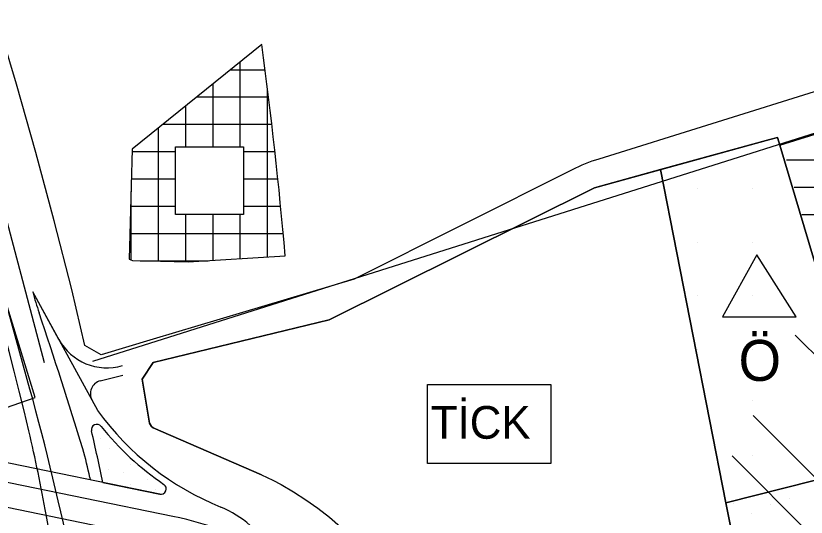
# Model space of a CAD drawing. Extents: x 409341 to 428634, y 4447481 to 4463281.
# Drawn here: x 420363.5 to 420653.1, y 4458345.7 to 4458529.4 of the extents above; entities that cross this region are included whole.
import ezdxf

# ---------------------------------------------------------------- set-up
doc = ezdxf.new("R2010")
doc.units = 0
for name, color, linetype in [('ADA', 7, 'Continuous'), ('ADAKENARI', 7, 'Continuous'), ('Default', 7, 'Continuous'), ('KALDIRIM', 7, 'Continuous'), ('Level 29', 7, 'Continuous'), ('LJ_SEMBOL', 7, 'Continuous'), ('OSB', 7, 'Continuous'), ('PL_AYA_PARK_DINLENME', 7, 'Continuous'), ('PL_EĞİTİM', 7, 'Continuous'), ('PL_KON_ONE_250', 7, 'Continuous'), ('PL_TİCK', 7, 'Continuous'), ('RAYLI_TOPLU_TAŞIMA_HATTI', 7, 'Continuous'), ('SN_BELEDIYE', 7, 'Continuous'), ('SN_TR_SIVILASMA', 7, 'Continuous'), ('TR_AKARYAKIT_SERVİS', 7, 'Continuous'), ('TR_EĞİTİM', 7, 'Continuous'), ('TR_ORTAGELISME', 7, 'Continuous'), ('TR_PARKALANI', 7, 'Continuous'), ('TR_TALIISMERK', 7, 'Continuous'), ('TR_TİCK', 7, 'Continuous')]:
    doc.layers.add(name, color=color, linetype=linetype)

# ---------------------------------------------------------------- blocks, each defined once
blk = doc.blocks.new('POINT_DISPLAY')
at = {"layer": 'Default'}
blk.add_line((0, 0), (0, 0), dxfattribs=at)

msp = doc.modelspace()

# ---------------------------------------------------------------- linework, layer by layer
at = {"layer": 'ADA'}
for p, q in [((420643.44, 4458481.99), (420732.53, 4458509.85)), ((420632.89, 4458304.12), (420599.65, 4458473.08))]:
    msp.add_line(p, q, dxfattribs=at)
for points in [[(420643.44, 4458481.99), (420659.49, 4458427.94), (420675.59, 4458370.42), (420677.32, 4458364.26), (420677.56, 4458363.39)], [(420623.66, 4458351.01), (420677.24, 4458364.55)]]:
    msp.add_lwpolyline(points, dxfattribs=at)
at = {"layer": 'ADAKENARI'}
for p, q in [((420847.49, 4458561.51), (420577.09, 4458476.96)), ((420363.78, 4458504.36), (420356.29, 4458529.2)), ((420370.89, 4458479.41), (420363.78, 4458504.36)), ((420575.45, 4458466.45), (420639.77, 4458484.06)), ((420575.45, 4458466.45), (420639.77, 4458484.06)), ((420639.77, 4458484.06), (420642.58, 4458484.9)), ((420642.58, 4458484.9), (420643.44, 4458481.99)), ((420377.62, 4458454.35), (420370.89, 4458479.41)), ((420567.31, 4458473.01), (420487.46, 4458432.9)), ((420383.98, 4458429.2), (420377.62, 4458454.35)), ((420487.46, 4458432.9), (420413.82, 4458410.91)), ((420388.84, 4458408.66), (420383.98, 4458429.2)), ((420394.78, 4458405.23), (420388.84, 4458408.66)), ((420413.82, 4458410.91), (420394.78, 4458405.23)), ((420413.22, 4458378.93), (420412.48, 4458380.21)), ((420416.22, 4458354.12), (420305.83, 4458376.8)), ((420416.22, 4458354.12), (420305.83, 4458376.8)), ((420413.84, 4458378.43), (420413.22, 4458378.93)), ((420453.57, 4458361.2), (420413.84, 4458378.43))]:
    msp.add_line(p, q, dxfattribs=at)
msp.add_lwpolyline([(420453.57, 4458361.2), (420457.65, 4458359.25), (420460.66, 4458357.68), (420465.3, 4458355), (420469.81, 4458352.11), (420474.18, 4458349.01), (420478.39, 4458345.7), (420482.45, 4458342.2), (420486.33, 4458338.51), (420490.35, 4458333.66), (420496.8, 4458325.83), (420501.73, 4458320.76), (420507.72, 4458316.16), (420514.7, 4458311.48), (420516.88, 4458310.01), (420522, 4458308.44), (420551.88, 4458303.07)], dxfattribs=at)
for centre, radius, start, end in [((420596.48, 4458414.92), 65, 107.3623, 116.6696), ((420393.2, 4458377.74), 2, 38.6563, 192.9963), ((420393.2, 4458377.74), 2, 38.6563, 192.9963), ((419493.85, 4458170.17), 921, 11.79266, 12.99632), ((419493.85, 4458170.17), 921, 11.79266, 12.99632), ((420476.76, 4458444.58), 105, 218.6563, 235.8038), ((420476.76, 4458444.58), 105, 218.6563, 235.8038), ((420416.62, 4458356.08), 2, 258.3886, 55.8038), ((420416.62, 4458356.08), 2, 258.3886, 55.8038)]:
    msp.add_arc(centre, radius, start, end, dxfattribs=at)
at = {"layer": 'KALDIRIM'}
for p, q in [((420379.27, 4458410.87), (420369.76, 4458428.28)), ((420393.5, 4458384.8), (420369.76, 4458428.28)), ((420379.27, 4458410.87), (420369.76, 4458428.28)), ((420393.5, 4458384.8), (420369.76, 4458428.28)), ((420421.02, 4458345.99), (420060.88, 4458419.99)), ((420421.02, 4458345.99), (420060.88, 4458419.99)), ((420423.3, 4458336.33), (420043.3, 4458414.41)), ((420423.3, 4458336.33), (420043.3, 4458414.41)), ((420394.42, 4458395.73), (420402.69, 4458397.74)), ((420393.5, 4458384.8), (420391.46, 4458388.54)), ((420390.62, 4458360.24), (420390.79, 4458359.35)), ((420390.62, 4458360.24), (420390.79, 4458359.35))]:
    msp.add_line(p, q, dxfattribs=at)
for centre, radius, start, end in [((420466.74, 4458452.67), 100, 194.1286, 198.7088), ((420466.74, 4458452.67), 100, 194.1286, 198.7088), ((418798.88, 4457887.84), 1660.9, 16.90173, 18.70883), ((418798.88, 4457887.84), 1660.9, 16.90173, 18.70883), ((420396.82, 4458420.45), 20, 208.633, 286.6245), ((420396.82, 4458420.45), 20, 208.633, 286.6245), ((420395.85, 4458390.94), 5, 106.6245, 208.633), ((420395.85, 4458390.94), 5, 106.6245, 208.633), ((420476.76, 4458444.58), 102.5, 215.6789, 248.1673), ((420476.76, 4458444.58), 102.5, 215.6789, 248.1673), ((420292.36, 4458341.64), 100, 10.7174, 16.9017), ((420292.36, 4458341.64), 100, 10.7174, 16.9017), ((420424.43, 4458315.18), 37.08, 28.2412, 67.4666), ((420424.43, 4458315.18), 37.08, 28.2412, 67.4666), ((420395.06, 4458219.63), 129, 40.973, 78.3886), ((420395.06, 4458219.63), 129, 40.973, 78.3886)]:
    msp.add_arc(centre, radius, start, end, dxfattribs=at)
at = {"layer": 'Level 29'}
for p, q in [((420478.28, 4458418.07), (420575.45, 4458466.45)), ((420413.8, 4458402.43), (420478.28, 4458418.07)), ((420409.77, 4458396.32), (420413.8, 4458402.43)), ((420412.48, 4458380.21), (420409.77, 4458396.32))]:
    msp.add_line(p, q, dxfattribs=at)
at = {"layer": 'LJ_SEMBOL'}
for p, q in [((420634.93, 4458441.88), (420622.38, 4458419.07)), ((420649.4, 4458419.07), (420634.93, 4458441.88)), ((420622.38, 4458419.07), (420649.4, 4458419.07))]:
    msp.add_line(p, q, dxfattribs=at)
at = {"layer": 'OSB'}
for points in [[(420374, 4458402.25), (420333.73, 4458554.43), (420007.65, 4459406.75), (419828, 4459907.45), (419873.71, 4459964.63), (419861.99, 4460046.05), (419800.79, 4460096.52), (419788.07, 4460171.32), (419687.29, 4460251.24), (419645.19, 4460319.68), (419562.32, 4460570.29)], [(421303.14, 4458521.03), (421213.37, 4458544.99), (420881.63, 4458557.8), (420391.63, 4458402.74)]]:
    msp.add_lwpolyline(points, dxfattribs=at)
at = {"layer": 'PL_AYA_PARK_DINLENME'}
for points in [[(420651.06, 4458305.46), (420782.27, 4458335.25), (420761.16, 4458405.89), (420743.03, 4458396.67), (420723.36, 4458386.67), (420703.69, 4458376.67), (420677.56, 4458363.39), (420677.32, 4458364.26), (420677.24, 4458364.55), (420623.66, 4458351.01), (420632.89, 4458304.12)], [(420395.41, 4458358.4), (420416.22, 4458354.12)]]:
    msp.add_lwpolyline(points, dxfattribs=at)
for centre, radius, start, end in [((420393.2, 4458377.74), 2, 38.6563, 192.9963), ((419493.85, 4458170.17), 921, 11.79266, 12.99632), ((420476.76, 4458444.58), 105, 218.6563, 235.8038), ((420416.62, 4458356.08), 2, 258.3886, 55.8038)]:
    msp.add_arc(centre, radius, start, end, dxfattribs=at)
at = {"layer": 'PL_EĞİTİM'}
msp.add_lwpolyline([(420677.24, 4458364.55), (420675.59, 4458370.42), (420659.49, 4458427.94), (420643.44, 4458481.99), (420642.58, 4458484.9), (420639.77, 4458484.06), (420599.65, 4458473.08), (420623.66, 4458351.01), (420677.24, 4458364.55)], dxfattribs=at)
at = {"layer": 'PL_KON_ONE_250'}
msp.add_lwpolyline([(420677.24, 4458364.55), (420677.32, 4458364.26), (420677.56, 4458363.39), (420703.69, 4458376.67), (420723.36, 4458386.67), (420743.03, 4458396.67), (420761.16, 4458405.89), (420783.99, 4458417.5), (420871.21, 4458460.84), (420847.49, 4458536.54), (420844.85, 4458544.96), (420732.53, 4458509.85), (420643.44, 4458481.99), (420659.49, 4458427.94), (420675.59, 4458370.42), (420677.24, 4458364.55)], dxfattribs=at)
at = {"layer": 'PL_TİCK'}
for points in [[(420599.65, 4458473.08), (420575.45, 4458466.45), (420478.28, 4458418.07), (420413.8, 4458402.43), (420409.77, 4458396.32), (420412.48, 4458380.21), (420413.22, 4458378.93), (420413.84, 4458378.43), (420453.57, 4458361.2), (420457.65, 4458359.25), (420460.66, 4458357.68), (420465.3, 4458355), (420469.81, 4458352.11), (420474.18, 4458349.01), (420478.39, 4458345.7), (420482.45, 4458342.2)], [(420632.89, 4458304.12), (420623.66, 4458351.01), (420599.65, 4458473.08)]]:
    msp.add_lwpolyline(points, dxfattribs=at)
at = {"layer": 'RAYLI_TOPLU_TAŞIMA_HATTI'}
msp.add_line((420368.69, 4458392.67), (420358.3, 4458430.33), dxfattribs=at)
for points in [[(420368.3, 4458377.35), (420366.58, 4458384.65), (420364.79, 4458391.94), (420362.94, 4458399.2), (420361.04, 4458406.46), (420359.1, 4458413.71), (420357.14, 4458420.94), (420355.15, 4458428.18), (420353.16, 4458435.41)], [(420383.81, 4458287.36), (420382.77, 4458294.79), (420381.72, 4458302.21), (420380.65, 4458309.64), (420379.55, 4458317.05), (420378.41, 4458324.47), (420377.22, 4458331.87), (420375.97, 4458339.27), (420374.65, 4458346.65)]]:
    msp.add_lwpolyline(points, dxfattribs=at)
for centre, radius, start, end in [((419404.76, 4458126.54), 1000, 11.56413, 15.43434), ((419686.18, 4458220.14), 700, 10.41238, 12.97881)]:
    msp.add_arc(centre, radius, start, end, dxfattribs=at)
at = {"layer": 'SN_BELEDIYE'}
msp.add_lwpolyline([(420056.61, 4458426.72), (420324.96, 4458373.69), (420370.63, 4458389.58), (420320.71, 4458552.35), (420275.22, 4458652.27), (420221.7, 4458795.24), (420100.91, 4458752.02), (420006.92, 4458544.31), (419990.62, 4458464.95)], dxfattribs=at)
at = {"layer": 'SN_TR_SIVILASMA'}
for p, q in [((420847.49, 4458213.94), (420649.01, 4458412.43)), ((420847.49, 4458169.04), (420633.61, 4458382.92)), ((420847.49, 4458146.59), (420625.91, 4458368.17))]:
    msp.add_line(p, q, dxfattribs=at)
at = {"layer": 'TR_AKARYAKIT_SERVİS'}
for p, q in [((420445.75, 4458481.46), (420445.75, 4458512.55)), ((420442.22, 4458509.7), (420454.84, 4458509.7)), ((420435.75, 4458481.46), (420435.75, 4458504.47)), ((420455.75, 4458441.07), (420455.75, 4458502.6)), ((420429.85, 4458499.7), (420456.1, 4458499.7)), ((420425.75, 4458481.46), (420425.75, 4458496.39)), ((420417.48, 4458489.7), (420457.3, 4458489.7)), ((420415.75, 4458439.53), (420415.75, 4458488.31)), ((420406.13, 4458479.7), (420422.04, 4458479.7)), ((420446.92, 4458479.7), (420458.44, 4458479.7)), ((420405.87, 4458469.7), (420422.04, 4458469.7)), ((420446.92, 4458469.7), (420459.52, 4458469.7)), ((420405.75, 4458439.96), (420405.75, 4458465.1)), ((420405.6, 4458459.7), (420422.04, 4458459.7)), ((420446.92, 4458459.7), (420460.53, 4458459.7)), ((420425.75, 4458439.26), (420425.75, 4458456.69)), ((420435.75, 4458439.81), (420435.75, 4458456.69)), ((420445.75, 4458440.44), (420445.75, 4458456.69)), ((420405.34, 4458449.7), (420461.48, 4458449.7)), ((420409.11, 4458439.7), (420433.98, 4458439.7))]:
    msp.add_line(p, q, dxfattribs=at)
for points in [[(420453.63, 4458518.92), (420406.16, 4458480.55), (420405.09, 4458440.21), (420406.21, 4458439.78), (420426.61, 4458439.24), (420462.22, 4458441.48)], [(420422.04, 4458456.69), (420422.04, 4458481.46), (420446.92, 4458481.46), (420446.92, 4458456.69), (420422.04, 4458456.69)]]:
    msp.add_lwpolyline(points, dxfattribs=at)
msp.add_arc((418818.45, 4458298.24), 1650, 4.9802, 7.68618, dxfattribs=at)
at = {"layer": 'TR_ORTAGELISME'}
for p, q in [((420645.85, 4458476.67), (420743.38, 4458476.67)), ((420648.65, 4458466.67), (420740.65, 4458466.67)), ((420651.45, 4458456.67), (420742.12, 4458456.67))]:
    msp.add_line(p, q, dxfattribs=at)
at = {"layer": 'TR_TALIISMERK'}
msp.add_lwpolyline([(420514.33, 4458394.37), (420559.45, 4458394.37), (420559.45, 4458365.34), (420514.33, 4458365.34)], close=True, dxfattribs=at)
at = {"layer": 'TR_TİCK'}
for points in [[(420623.66, 4458351.01), (420599.65, 4458473.08), (420575.45, 4458466.45), (420478.28, 4458418.07), (420413.8, 4458402.43), (420409.77, 4458396.32), (420412.48, 4458380.21), (420413.22, 4458378.93), (420413.84, 4458378.43), (420453.57, 4458361.2), (420457.65, 4458359.25), (420460.66, 4458357.68), (420465.3, 4458355), (420469.81, 4458352.11), (420474.18, 4458349.01), (420478.39, 4458345.7), (420482.45, 4458342.2)], [(420514.33, 4458365.34), (420514.33, 4458394.37), (420559.45, 4458394.37), (420559.45, 4458365.34), (420514.33, 4458365.34)], [(420632.89, 4458304.12), (420623.66, 4458351.01)]]:
    msp.add_lwpolyline(points, dxfattribs=at)

# ---------------------------------------------------------------- block references
at = {"layer": 'TR_EĞİTİM', "xscale": 0.1, "yscale": 0.10000000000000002}
for p in [(420613.27, 4458466.19), (420633.51, 4458466.19), (420613.27, 4458446.19), (420633.51, 4458446.19), (420613.27, 4458427.11), (420633.51, 4458427.11), (420613.27, 4458407.11), (420633.51, 4458407.11), (420633.51, 4458388.4), (420633.51, 4458368.4)]:
    msp.add_blockref('POINT_DISPLAY', p, dxfattribs=at)
at = {"layer": 'TR_PARKALANI', "xscale": 0.1, "yscale": 0.10000000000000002}
for p in [(420394.46, 4458374.4), (420397.95, 4458370.75), (420397.64, 4458363.01), (420405.69, 4458364.98), (420402.96, 4458361.95), (420411.92, 4458359.52), (420405.54, 4458357.69), (420414.65, 4458355.72), (420646.82, 4458352.65), (420626.52, 4458350.56), (420640.09, 4458350.3), (420632.86, 4458347.07)]:
    msp.add_blockref('POINT_DISPLAY', p, dxfattribs=at)

# ---------------------------------------------------------------- texts
at = {"layer": 'LJ_SEMBOL'}
msp.add_text('Ö', height=15, dxfattribs=at).set_placement((420628.27, 4458395.65))
at = {"layer": 'TR_TALIISMERK'}
msp.add_text('TİCK', height=12, dxfattribs=at).set_placement((420515.54, 4458374.45))

doc.saveas('drawing.dxf')
